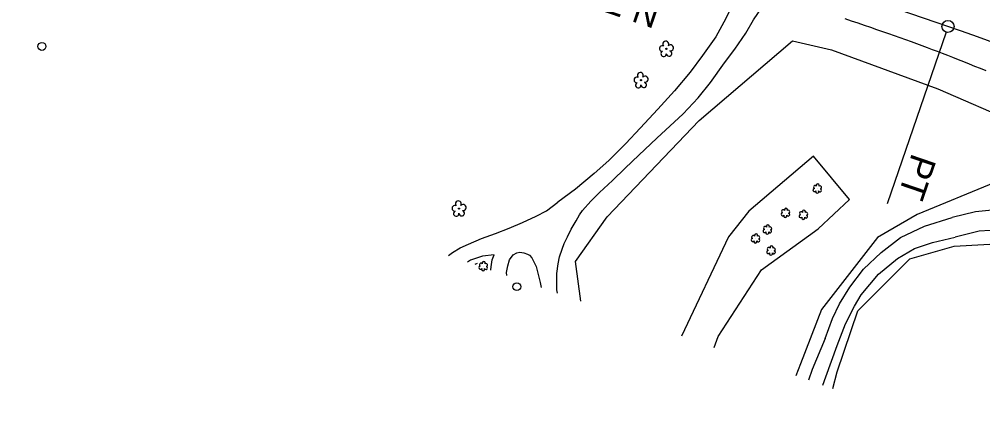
# Model space of a CAD drawing. Extents: x 478596 to 483012, y 490885 to 495165.
# Drawn here: x 479936 to 480534, y 493041 to 493288 of the extents above; entities that cross this region are included whole.
import ezdxf

# ---------------------------------------------------------------- set-up
doc = ezdxf.new("R2010")
doc.units = 0
for name, color, linetype in [('Exist Horizontal Alignment', 7, 'Continuous'), ('Exist Horizontal Alignment Direction Label', 7, 'Continuous'), ('Exist Other Culture Fence Line', 7, 'Continuous'), ('Exist Roads EOP', 7, 'Continuous'), ('Exist Roads Soil', 7, 'Continuous'), ('Exist Utilities Other Pole CELL', 7, 'Continuous'), ('Exist Vegetation Shrub CELL', 7, 'Continuous'), ('Exist Vegetation Tree CELL', 7, 'Continuous'), ('Exist Vegetation Woods Line', 7, 'Continuous')]:
    doc.layers.add(name, color=color, linetype=linetype)

msp = doc.modelspace()

# ---------------------------------------------------------------- linework, layer by layer
at = {"layer": 'Exist Horizontal Alignment'}
for p, q in [((480512.88, 493283.24), (479885.83, 493498.07)), ((480511.67, 493279.69), (480475.13, 493173.05))]:
    msp.add_line(p, q, dxfattribs=at)
msp.add_circle((480512.88, 493283.24), 3.75, dxfattribs=at)
msp.add_arc((480184.05, 492323.44), 1014.56, 56.41358, 71.08844, dxfattribs=at)
at = {"layer": 'Exist Other Culture Fence Line'}
msp.add_lwpolyline([(480220.27, 493136.08), (480218.88, 493135.31)], dxfattribs=at)
at = {"layer": 'Exist Roads EOP'}
msp.add_lwpolyline([(480536.52, 493255.67), (480533.07, 493257.05), (480529.63, 493258.44), (480526.19, 493259.81), (480522.76, 493261.19), (480519.34, 493262.55), (480515.97, 493263.89), (480512.69, 493265.18), (480509.5, 493266.41), (480506.41, 493267.6), (480503.31, 493268.77), (480500.13, 493269.95), (480496.86, 493271.15), (480493.52, 493272.37), (480490.11, 493273.6), (480486.66, 493274.83), (480483.18, 493276.08), (480479.66, 493277.33), (480476.08, 493278.6), (480472.42, 493279.88), (480468.68, 493281.18), (480464.86, 493282.48), (480460.96, 493283.81), (480457.01, 493285.17), (480453, 493286.56), (480448.93, 493287.97)], dxfattribs=at)
at = {"layer": 'Exist Roads Soil'}
for points in [[(480368.47, 493315.7), (480372.2, 493311.19), (480374.68, 493307.77), (480376.25, 493304.93), (480377.27, 493302.24), (480377.66, 493299.47), (480377.56, 493295.06), (480376.57, 493291.86), (480373.63, 493285.78), (480368.64, 493276.85), (480360.22, 493265.24), (480352.54, 493254.89), (480342.85, 493243.21), (480332.52, 493231.82), (480321.57, 493220.07), (480312.67, 493210.45), (480302.04, 493199.87), (480292.9, 493191.8), (480281.27, 493182.16), (480270.34, 493174.05)], [(480270.16, 493117.57), (480269.77, 493119.69), (480269.66, 493129.78), (480270.49, 493135.74), (480271.43, 493140.24), (480273.03, 493144.98), (480274.34, 493148.48), (480276.46, 493152.51), (480278.61, 493157.26), (480281.75, 493162.53), (480283.85, 493166.14), (480285.6, 493168.99), (480290.82, 493174.82), (480296.17, 493180.19), (480304.3, 493187.64), (480312.13, 493195.23), (480320.8, 493203.33), (480331.99, 493213.77), (480348.18, 493229.02), (480357.6, 493238.86), (480365.16, 493248.45), (480374.04, 493260.57), (480380.43, 493269.01), (480387.21, 493279.07), (480392.07, 493287.3), (480397.28, 493295.14)], [(480202.4, 493141.01), (480204.89, 493142.82), (480209.58, 493145.71), (480214.85, 493148.11), (480222.86, 493151.5), (480231.64, 493154.58), (480240.06, 493158.02), (480248.31, 493161.42), (480256.86, 493165.31), (480263.23, 493168.66), (480270.34, 493174.05)], [(480731.82, 493053.11), (480721.95, 493066.73), (480709.7, 493082.22), (480698.12, 493096.69), (480685.79, 493110.1), (480672.35, 493122.67), (480658.28, 493134.4), (480644.84, 493144.43), (480631.58, 493152.79), (480621.79, 493157.74), (480612.16, 493161.4), (480591.29, 493167.1), (480577.43, 493169.3), (480560.94, 493170.49), (480544.44, 493169.56), (480529.92, 493168.05), (480515.54, 493164.56)], [(480436.43, 493089.54), (480441.02, 493101.89), (480445.49, 493110.96), (480451.87, 493121.3), (480460.33, 493132.43), (480471.3, 493142.88), (480483.33, 493152.18), (480498.22, 493159.19), (480515.54, 493164.56)], [(480720.54, 493049.96), (480707.27, 493066.03), (480692.47, 493084.33), (480679.65, 493098.24), (480666.2, 493112.15), (480653.49, 493123.18), (480641.49, 493133), (480629.04, 493141.05), (480621.09, 493145.28), (480609.33, 493150.38), (480596.94, 493154), (480584.65, 493155.73), (480573.41, 493156.71), (480558.54, 493157.03), (480546, 493156.86), (480532.21, 493155.99), (480517.3, 493152.44)], [(480444.05, 493084.99), (480449.23, 493098.45), (480454.69, 493109.55), (480458.91, 493116.51), (480469.58, 493129.4), (480481.48, 493139.21), (480491.97, 493145.42), (480503.22, 493149.14), (480517.3, 493152.44)], [(480228.78, 493131.88), (480228.81, 493132.2), (480229.2, 493135.47), (480229.62, 493138.38), (480230.78, 493141.48), (480223.54, 493140.5), (480216.11, 493138.07), (480214.15, 493136.94)], [(480238.61, 493128.48), (480238.45, 493130.44), (480239.19, 493134.62), (480240.42, 493138.31), (480242.6, 493141.39), (480244.96, 493142.66), (480246.84, 493143.13), (480249.2, 493142.6), (480251.5, 493141.72), (480252.71, 493141.15), (480254.2, 493139.57), (480256.84, 493134.21), (480259.36, 493124.25), (480260, 493121.08)], [(480436.43, 493089.54), (480428.52, 493070.22), (480426.18, 493063.59)], [(480435.06, 493060.52), (480436.88, 493065.6), (480444.05, 493084.99)]]:
    msp.add_lwpolyline(points, dxfattribs=at)
at = {"layer": 'Exist Utilities Other Pole CELL'}
for centre in [(479949.72, 493270.8), (480244.87, 493121.62)]:
    msp.add_circle(centre, 2.46, dxfattribs=at)
at = {"layer": 'Exist Vegetation Shrub CELL'}
for p, q in [((480431.7, 493182.37), (480431.7, 493182.37)), ((480411.91, 493167.28), (480411.91, 493167.28)), ((480423.08, 493166.08), (480423.08, 493166.08)), ((480400.7, 493156.9), (480400.7, 493156.9)), ((480393.3, 493151.33), (480393.3, 493151.33)), ((480402.99, 493143.88), (480402.99, 493143.88)), ((480224.04, 493134.17), (480224.04, 493134.17))]:
    msp.add_line(p, q, dxfattribs=at)
for centre, radius, start, end in [((480429.9, 493181.67), 0.955, 95.10992, 327.95341), ((480430.22, 493183.5), 0.968, 35.89076, 245.42165), ((480431.57, 493180.69), 0.984, 151.27966, 21.38702), ((480431.93, 493184.41), 0.99, 334.83907, 200.47174), ((480433.34, 493181.44), 0.937, 204.99133, 73.46012), ((480433.38, 493183.24), 0.929, 284.45672, 126.08612), ((480410.43, 493168.4), 0.968, 35.89076, 245.42165), ((480412.14, 493169.32), 0.99, 334.83907, 200.47174), ((480413.59, 493168.14), 0.929, 284.45672, 126.08612), ((480423.31, 493168.12), 0.99, 334.83907, 200.47174), ((480410.11, 493166.57), 0.955, 95.10992, 327.95341), ((480411.79, 493165.59), 0.984, 151.27966, 21.38702), ((480413.55, 493166.35), 0.937, 204.99133, 73.46012), ((480421.28, 493165.38), 0.955, 95.10992, 327.95341), ((480421.6, 493167.21), 0.968, 35.89076, 245.42165), ((480422.96, 493164.4), 0.984, 151.27966, 21.38702), ((480424.72, 493165.15), 0.937, 204.99133, 73.46012), ((480424.76, 493166.95), 0.929, 284.45672, 126.08612), ((480398.9, 493156.2), 0.955, 95.10992, 327.95341), ((480399.22, 493158.03), 0.968, 35.89076, 245.42165), ((480400.93, 493158.95), 0.99, 334.83907, 200.47174), ((480402.34, 493155.98), 0.937, 204.99133, 73.46012), ((480402.37, 493157.77), 0.929, 284.45672, 126.08612), ((480391.5, 493150.63), 0.955, 95.10992, 327.95341), ((480391.81, 493152.46), 0.968, 35.89076, 245.42165), ((480393.53, 493153.37), 0.99, 334.83907, 200.47174), ((480394.93, 493150.4), 0.937, 204.99133, 73.46012), ((480394.97, 493152.2), 0.929, 284.45672, 126.08612), ((480400.57, 493155.22), 0.984, 151.27966, 21.38702), ((480393.17, 493149.65), 0.984, 151.27966, 21.38702), ((480401.51, 493145), 0.968, 35.89076, 245.42165), ((480403.22, 493145.92), 0.99, 334.83907, 200.47174), ((480404.66, 493144.75), 0.929, 284.45672, 126.08612), ((480401.19, 493143.17), 0.955, 95.10992, 327.95341), ((480402.86, 493142.19), 0.984, 151.27966, 21.38702), ((480404.63, 493142.95), 0.937, 204.99133, 73.46012), ((480222.24, 493133.46), 0.955, 95.10992, 327.95341), ((480222.56, 493135.29), 0.968, 35.89076, 245.42165), ((480223.92, 493132.48), 0.984, 151.27966, 21.38702), ((480224.27, 493136.21), 0.99, 334.83907, 200.47174), ((480225.68, 493133.24), 0.937, 204.99133, 73.46012), ((480225.72, 493135.04), 0.929, 284.45672, 126.08612)]:
    msp.add_arc(centre, radius, start, end, dxfattribs=at)
at = {"layer": 'Exist Vegetation Tree CELL'}
for p, q in [((480337.83, 493269.32), (480337.83, 493269.32)), ((480322.04, 493249.85), (480322.04, 493249.85)), ((480208.92, 493170.12), (480208.92, 493170.12))]:
    msp.add_line(p, q, dxfattribs=at)
for centre in [(480337.83, 493269.32), (480322.04, 493249.85), (480208.92, 493170.12)]:
    msp.add_circle(centre, 0.326, dxfattribs=at)
for centre, radius, start, end in [((480335.23, 493269.47), 1.73, 62.66361, 279.3457), ((480337.45, 493272.19), 1.86, 330.16508, 219.71335), ((480340.38, 493269.91), 1.9, 257.1011, 134.19993), ((480336.13, 493266.2), 1.69, 111.56708, 6.23104), ((480339.5, 493266.42), 1.7, 181.28216, 74.55999), ((480321.66, 493252.72), 1.86, 330.16508, 219.71335), ((480324.59, 493250.44), 1.9, 257.1011, 134.19993), ((480319.44, 493250), 1.73, 62.66361, 279.3457), ((480320.34, 493246.73), 1.69, 111.56708, 6.23104), ((480323.72, 493246.95), 1.7, 181.28216, 74.55999), ((480208.53, 493173), 1.86, 330.16508, 219.71335), ((480206.31, 493170.28), 1.73, 62.66361, 279.3457), ((480207.21, 493167), 1.69, 111.56708, 6.23104), ((480210.59, 493167.22), 1.7, 181.28216, 74.55999), ((480211.47, 493170.71), 1.9, 257.1011, 134.19993)]:
    msp.add_arc(centre, radius, start, end, dxfattribs=at)
at = {"layer": 'Exist Vegetation Woods Line'}
for points in [[(480284.75, 493112.52), (480281.32, 493137.32), (480300.99, 493164.93), (480358.3, 493224.84), (480416.2, 493274.34), (480440.45, 493268.72)], [(480440.45, 493268.72), (480506.54, 493244.38), (480603.86, 493202.26), (480669.06, 493167.83), (480758.97, 493102.29)], [(480451.7, 493175.7), (480429.33, 493202.6), (480389.06, 493168.44), (480376.44, 493152.64), (480347.29, 493090.89)], [(480730.58, 493076.57), (480702.59, 493110.84), (480669.75, 493139.99), (480632.94, 493165.71), (480582.98, 493183.96), (480541.91, 493186.28), (480493.77, 493166.45), (480469.01, 493152.06), (480434.17, 493107.43), (480421.28, 493073.75), (480418.33, 493066.31)], [(480367.52, 493083.89), (480370.08, 493090.75), (480397.03, 493132.05), (480432.11, 493157.5), (480451.7, 493175.7)], [(480441.22, 493058.39), (480444.06, 493068.65), (480456.79, 493106.6), (480489.18, 493138.92), (480516.69, 493146.78), (480564.5, 493149.4), (480601.45, 493145.09), (480635.06, 493127.16), (480668.43, 493099.05), (480716.65, 493041.49)]]:
    msp.add_lwpolyline(points, dxfattribs=at)

# ---------------------------------------------------------------- texts
at = {"layer": 'Exist Horizontal Alignment'}
msp.add_text('PT', height=16, rotation=251.08844, dxfattribs=at).set_placement((480490.67, 493205.07))
at = {"layer": 'Exist Horizontal Alignment Direction Label'}
msp.add_text('N 71%%d 05\' 18" W', height=16, rotation=161.08844, dxfattribs=at).set_placement((480335.3, 493296.82))

doc.saveas('drawing.dxf')
